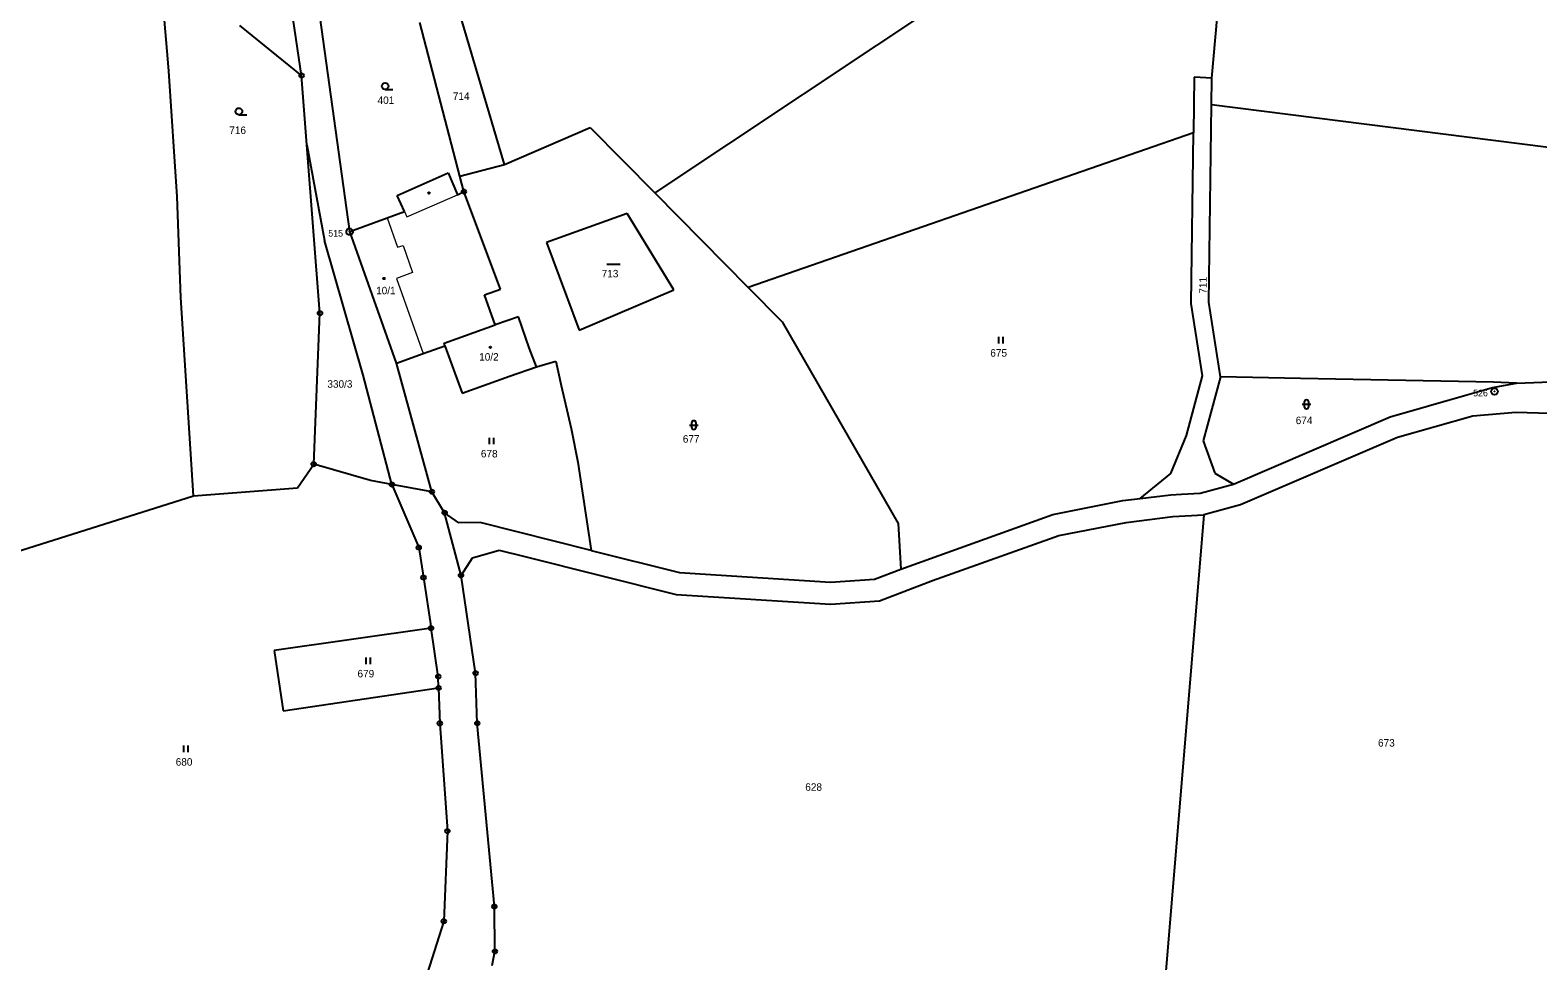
# Model space of a CAD drawing. Extents: x -719614 to -717765, y -1095834 to -1093862.
# Drawn here: x -719079.2 to -718737.1, y -1094701.4 to -1094490.2 of the extents above; entities that cross this region are included whole.
import ezdxf
from ezdxf.enums import TextEntityAlignment as Align

# ---------------------------------------------------------------- set-up
doc = ezdxf.new("R2010")
doc.units = 0
doc.header["$LTSCALE"] = 0.68
for name, color, linetype, lineweight in [('1', 7, 'Continuous', 25), ('3', 7, 'Continuous', 25), ('4', 7, 'Continuous', 13), ('5', 7, 'Continuous', 25), ('8', 7, 'Continuous', 25)]:
    doc.layers.add(name, color=color, linetype=linetype, lineweight=lineweight)
doc.layers.add('2', color=7, linetype='Continuous')

msp = doc.modelspace()

# ---------------------------------------------------------------- linework, layer by layer
at = {"layer": '1'}
for p, q in [((-718811.08, -1094501.08), (-718807.67, -1094463.47)), ((-719048.5, -1094490.56), (-719049.85, -1094474.97)), ((-718861.16, -1094476.31), (-718937.45, -1094527.15)), ((-719006.69, -1094535.86), (-719013.75, -1094484.64)), ((-719017.63, -1094500.49), (-719019.84, -1094485.67)), ((-718981.69, -1094523.35), (-718990.77, -1094488.5)), ((-718971.55, -1094520.7), (-718981.41, -1094487.48)), ((-719047.97, -1094496.68), (-719048.5, -1094490.56)), ((-719017.63, -1094500.49), (-719031.6, -1094489.15)), ((-719047.73, -1094499.49), (-719047.97, -1094496.68)), ((-719045.87, -1094527.94), (-719047.73, -1094499.49)), ((-719016.41, -1094516.26), (-719017.63, -1094500.49)), ((-718815.08, -1094500.87), (-718815.25, -1094513.52)), ((-718811.08, -1094501.08), (-718815.08, -1094500.87)), ((-718811.16, -1094507.18), (-718811.08, -1094501.08)), ((-718811.76, -1094551.92), (-718811.16, -1094507.18)), ((-718631.67, -1094529.78), (-718811.16, -1094507.18)), ((-718971.55, -1094520.7), (-718952.12, -1094512.28)), ((-718952.12, -1094512.28), (-718937.45, -1094527.15)), ((-719016.41, -1094516.26), (-719012.4, -1094537.94)), ((-719013.45, -1094554.42), (-719016.41, -1094516.26)), ((-718815.25, -1094513.52), (-718916.28, -1094548.62)), ((-718815.76, -1094552.2), (-718815.25, -1094513.52)), ((-718995.96, -1094527.73), (-718984.36, -1094522.6)), ((-718984.36, -1094522.6), (-718982.24, -1094527.55)), ((-718981.69, -1094523.35), (-718971.55, -1094520.7)), ((-718980.78, -1094526.83), (-718981.69, -1094523.35)), ((-719045.05, -1094550.89), (-719045.87, -1094527.94)), ((-718994.31, -1094531.38), (-718995.96, -1094527.73)), ((-718982.24, -1094527.55), (-718980.78, -1094526.83)), ((-718972.48, -1094548.97), (-718980.78, -1094526.83)), ((-718937.45, -1094527.15), (-718916.28, -1094548.62)), ((-719006.69, -1094535.86), (-718998.18, -1094532.81)), ((-718998.18, -1094532.81), (-718994.31, -1094531.38)), ((-718943.74, -1094531.8), (-718962.09, -1094538.35)), ((-718933.19, -1094549.13), (-718943.74, -1094531.8)), ((-718996.07, -1094565.77), (-719006.69, -1094535.86)), ((-719003.62, -1094568.52), (-719012.4, -1094537.94)), ((-718962.09, -1094538.35), (-718954.61, -1094558.25)), ((-718976.15, -1094550.29), (-718972.48, -1094548.97)), ((-718973.68, -1094557.1), (-718976.15, -1094550.29)), ((-718954.61, -1094558.25), (-718933.19, -1094549.13)), ((-718916.28, -1094548.62), (-718908.6, -1094556.41)), ((-719042.13, -1094595.83), (-719045.05, -1094550.89)), ((-718813.24, -1094568.66), (-718815.76, -1094552.2)), ((-718809.16, -1094568.88), (-718811.76, -1094551.92)), ((-719014.88, -1094588.67), (-719013.45, -1094554.42)), ((-718985.3, -1094561.22), (-718973.68, -1094557.1)), ((-718968.42, -1094555.22), (-718973.68, -1094557.1)), ((-718965.97, -1094562.29), (-718968.42, -1094555.22)), ((-718908.6, -1094556.41), (-718882.25, -1094602.15)), ((-718996.07, -1094565.77), (-718990.06, -1094563.59)), ((-718990.06, -1094563.59), (-718985.1, -1094561.8)), ((-718985.1, -1094561.8), (-718985.3, -1094561.22)), ((-718985.1, -1094561.8), (-718981.21, -1094572.6)), ((-718964.34, -1094566.56), (-718965.97, -1094562.29)), ((-718988.05, -1094594.94), (-718996.07, -1094565.77)), ((-718970.44, -1094568.68), (-718964.34, -1094566.56)), ((-718964.34, -1094566.56), (-718959.94, -1094565.28)), ((-718959.94, -1094565.28), (-718958.76, -1094570.82)), ((-718997.11, -1094593.3), (-719003.62, -1094568.52)), ((-718981.21, -1094572.6), (-718970.44, -1094568.68)), ((-718958.76, -1094570.82), (-718956.46, -1094580.57)), ((-718816.83, -1094582.14), (-718813.24, -1094568.66)), ((-718809.16, -1094568.88), (-718813.03, -1094583.41)), ((-718791, -1094569.25), (-718809.16, -1094568.88)), ((-718747.21, -1094570.06), (-718791, -1094569.25)), ((-718747.39, -1094571.27), (-718742, -1094570.33)), ((-718742, -1094570.33), (-718747.21, -1094570.06)), ((-718742, -1094570.33), (-718732.24, -1094569.91)), ((-718770.62, -1094577.94), (-718753.22, -1094572.94)), ((-718753.22, -1094572.94), (-718747.39, -1094571.27)), ((-718806.21, -1094593.2), (-718770.62, -1094577.94)), ((-718751.84, -1094577.75), (-718768.94, -1094582.66)), ((-718742.11, -1094576.99), (-718751.84, -1094577.75)), ((-718722.78, -1094577.46), (-718742.11, -1094576.99)), ((-718956.46, -1094580.57), (-718954.96, -1094588.2)), ((-718820.37, -1094590.82), (-718816.83, -1094582.14)), ((-718813.03, -1094583.41), (-718810.4, -1094590.74)), ((-718768.94, -1094582.66), (-718804.57, -1094597.94)), ((-718954.96, -1094588.2), (-718951.94, -1094608.25)), ((-719018.53, -1094594.04), (-719014.88, -1094588.67)), ((-719001.95, -1094592.42), (-719014.88, -1094588.67)), ((-718827.36, -1094596.46), (-718820.37, -1094590.82)), ((-718810.4, -1094590.74), (-718806.21, -1094593.2)), ((-719042.13, -1094595.83), (-719018.53, -1094594.04)), ((-718997.11, -1094593.3), (-719001.95, -1094592.42)), ((-718997.11, -1094593.3), (-718991.03, -1094607.6)), ((-718988.05, -1094594.94), (-718997.11, -1094593.3)), ((-718985.16, -1094599.69), (-718988.05, -1094594.94)), ((-718813.71, -1094595.22), (-718806.21, -1094593.2)), ((-719125.67, -1094622.21), (-719042.13, -1094595.83)), ((-718847.14, -1094600.06), (-718831.31, -1094596.95)), ((-718831.31, -1094596.95), (-718827.36, -1094596.46)), ((-718827.36, -1094596.46), (-718820.37, -1094595.6)), ((-718820.37, -1094595.6), (-718817.94, -1094595.46)), ((-718817.94, -1094595.46), (-718813.71, -1094595.22)), ((-718804.57, -1094597.94), (-718812.91, -1094600.18)), ((-718981.45, -1094613.92), (-718985.16, -1094599.69)), ((-718981.95, -1094601.97), (-718985.16, -1094599.69)), ((-718977.14, -1094601.92), (-718981.95, -1094601.97)), ((-718951.94, -1094608.25), (-718977.14, -1094601.92)), ((-718881.62, -1094612.47), (-718847.14, -1094600.06)), ((-718845.8, -1094604.89), (-718830.52, -1094601.89)), ((-718830.52, -1094601.89), (-718819.92, -1094600.58)), ((-718812.91, -1094600.18), (-718822.27, -1094712.18)), ((-718819.92, -1094600.58), (-718812.91, -1094600.18)), ((-718882.25, -1094602.15), (-718881.62, -1094612.47)), ((-718874.44, -1094615.08), (-718845.8, -1094604.89)), ((-718991.03, -1094607.6), (-718989.97, -1094614.4)), ((-718978.88, -1094609.9), (-718972.79, -1094608.17)), ((-718972.79, -1094608.17), (-718966.97, -1094609.63)), ((-718951.94, -1094608.25), (-718931.86, -1094613.29)), ((-718981.45, -1094613.92), (-718978.88, -1094609.9)), ((-718966.97, -1094609.63), (-718932.63, -1094618.25)), ((-718989.97, -1094614.4), (-718988.26, -1094625.89)), ((-718978.14, -1094636.09), (-718981.45, -1094613.92)), ((-718931.86, -1094613.29), (-718897.62, -1094615.42)), ((-718897.62, -1094615.42), (-718887.6, -1094614.75)), ((-718887.6, -1094614.75), (-718881.62, -1094612.47)), ((-718886.52, -1094619.69), (-718874.44, -1094615.08)), ((-718932.63, -1094618.25), (-718897.61, -1094620.43)), ((-718897.61, -1094620.43), (-718886.52, -1094619.69)), ((-718988.26, -1094625.89), (-719023.84, -1094630.93)), ((-718986.62, -1094636.85), (-718988.26, -1094625.89)), ((-719023.84, -1094630.93), (-719021.8, -1094644.68)), ((-718977.76, -1094647.46), (-718978.14, -1094636.09)), ((-719021.8, -1094644.68), (-718986.53, -1094639.44)), ((-718986.53, -1094639.44), (-718986.62, -1094636.85)), ((-718986.53, -1094639.44), (-718986.26, -1094647.48)), ((-718986.26, -1094647.48), (-718984.53, -1094671.93)), ((-718973.88, -1094689.05), (-718977.76, -1094647.46)), ((-718984.53, -1094671.93), (-718985.35, -1094692.38)), ((-718973.75, -1094699.22), (-718973.88, -1094689.05)), ((-718985.35, -1094692.38), (-718989.11, -1094704.27)), ((-718974.35, -1094702.44), (-718973.75, -1094699.22))]:
    msp.add_line(p, q, dxfattribs=at)
at = {"layer": '3'}
for p, q in [((-718998.663, -1094503.64), (-718996.913, -1094503.64)), ((-719031.833, -1094509.38), (-719030.083, -1094509.38)), ((-718948.348, -1094543.32), (-718945.348, -1094543.32)), ((-718859.451, -1094561.3), (-718859.451, -1094559.8)), ((-718858.45, -1094561.3), (-718858.45, -1094559.8)), ((-718790.611, -1094575.101), (-718788.609, -1094575.101)), ((-718790.111, -1094574.601), (-718790.111, -1094575.602)), ((-718789.109, -1094575.602), (-718789.109, -1094574.601)), ((-718929.631, -1094579.811), (-718927.629, -1094579.811)), ((-718929.131, -1094579.311), (-718929.131, -1094580.312)), ((-718928.129, -1094580.312), (-718928.129, -1094579.311)), ((-718975.021, -1094584.17), (-718975.021, -1094582.67)), ((-718974.02, -1094584.17), (-718974.02, -1094582.67)), ((-719002.991, -1094634.08), (-719002.991, -1094632.58)), ((-719001.99, -1094634.08), (-719001.99, -1094632.58)), ((-719044.331, -1094654.04), (-719044.331, -1094652.54)), ((-719043.33, -1094654.04), (-719043.33, -1094652.54))]:
    msp.add_line(p, q, dxfattribs=at)
for centre in [(-718998.6629, -1094502.8898), (-719031.8329, -1094508.6298)]:
    msp.add_circle(centre, 0.75, dxfattribs=at)
for centre, start, end in [((-718789.61, -1094574.6009), 0, 180), ((-718789.61, -1094575.6009), 180, 359.98789), ((-718928.63, -1094579.3109), 0, 180), ((-718928.63, -1094580.3109), 180, 359.98789)]:
    msp.add_arc(centre, 0.5, start, end, dxfattribs=at)
at = {"layer": '4'}
for p, q in [((-718993.77, -1094532.59), (-718982.24, -1094527.55)), ((-718998.18, -1094532.81), (-718995.84, -1094539.41)), ((-718994.31, -1094531.38), (-718993.77, -1094532.59)), ((-718995.84, -1094539.41), (-718994.6, -1094539.03)), ((-718994.6, -1094539.03), (-718992.43, -1094545.2)), ((-718992.43, -1094545.2), (-718996.09, -1094546.53)), ((-718996.09, -1094546.53), (-718990.06, -1094563.59))]:
    msp.add_line(p, q, dxfattribs=at)
at = {"layer": '5'}
for centre in [(-718988.7368, -1094527.1692), (-718998.9268, -1094546.5592), (-718974.7868, -1094562.1792)]:
    msp.add_circle(centre, 0.175, dxfattribs=at)
at = {"layer": '8'}
for centre, radius in [((-719017.63, -1094500.4899), 0.5), ((-719017.63, -1094500.4899), 0.0303), ((-718980.78, -1094526.8299), 0.5), ((-718980.78, -1094526.8299), 0.0303), ((-719006.72, -1094535.9298), 0.75), ((-719006.72, -1094535.9298), 0.03), ((-719013.45, -1094554.4199), 0.5), ((-719013.45, -1094554.4199), 0.0303), ((-718746.96, -1094572.1798), 0.75), ((-718746.96, -1094572.1798), 0.03), ((-719014.88, -1094588.6699), 0.5), ((-719014.88, -1094588.6699), 0.0303), ((-718997.11, -1094593.2999), 0.5), ((-718997.11, -1094593.2999), 0.0303), ((-718988.05, -1094594.9399), 0.5), ((-718988.05, -1094594.9399), 0.0303), ((-718985.16, -1094599.6899), 0.5), ((-718985.16, -1094599.6899), 0.0303), ((-718991.03, -1094607.5999), 0.5), ((-718991.03, -1094607.5999), 0.0303), ((-718989.97, -1094614.3999), 0.5), ((-718989.97, -1094614.3999), 0.0303), ((-718981.45, -1094613.9199), 0.5), ((-718981.45, -1094613.9199), 0.0303), ((-718988.26, -1094625.8899), 0.5), ((-718988.26, -1094625.8899), 0.0303), ((-718978.14, -1094636.0899), 0.5), ((-718978.14, -1094636.0899), 0.0303), ((-718986.62, -1094636.8499), 0.5), ((-718986.53, -1094639.4399), 0.5), ((-718986.62, -1094636.8499), 0.0303), ((-718986.53, -1094639.4399), 0.0303), ((-718986.26, -1094647.4799), 0.5), ((-718986.26, -1094647.4799), 0.0303), ((-718977.76, -1094647.4599), 0.5), ((-718977.76, -1094647.4599), 0.0303), ((-718984.53, -1094671.9299), 0.5), ((-718984.53, -1094671.9299), 0.0303), ((-718973.88, -1094689.0499), 0.5), ((-718973.88, -1094689.0499), 0.0303), ((-718985.35, -1094692.3799), 0.5), ((-718985.35, -1094692.3799), 0.0303), ((-718973.75, -1094699.2199), 0.5), ((-718973.75, -1094699.2199), 0.0303)]:
    msp.add_circle(centre, radius, dxfattribs=at)

# ---------------------------------------------------------------- texts
at = {"layer": '2'}
for s, p in [('401', (-718998.489, -1094506.955)), ('714', (-718981.409, -1094506.022)), ('716', (-719032.129, -1094513.762)), ('713', (-718947.639, -1094546.302)), ('10/1', (-718998.499, -1094550.135)), ('10/2', (-718975.119, -1094565.185)), ('675', (-718859.459, -1094564.282)), ('330/3', (-719008.93, -1094571.335)), ('674', (-718790.159, -1094579.592)), ('677', (-718929.229, -1094583.792)), ('678', (-718975.049, -1094587.152)), ('679', (-719003.039, -1094637.062)), ('673', (-718771.489, -1094652.752)), ('680', (-719044.289, -1094657.082)), ('628', (-718901.439, -1094662.782))]:
    msp.add_text(s, height=1.7, dxfattribs=at).set_placement(p, align=Align.CENTER)
msp.add_text('711', height=1.7, rotation=90, dxfattribs=at).set_placement((-718812.257, -1094548.089), align=Align.CENTER)
at = {"layer": '8'}
for s, p in [('515', (-719008.219, -1094537.047)), ('526', (-718748.459, -1094573.297))]:
    msp.add_text(s, height=1.5, dxfattribs=at).set_placement(p, align=Align.RIGHT)

doc.saveas('drawing.dxf')
